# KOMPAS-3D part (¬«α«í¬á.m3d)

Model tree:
1. Эскиз:1
2. Операция выдавливания:1
     Расстояние 1 = 5
3. Скругление:1
     Радиус = 1
4. Эскиз:2
5. Операция выдавливания:2
     Расстояние 1 = 0.1
6. Скругление:2
     Радиус = 0.1
7. Эскиз:3
8. Операция выдавливания:3
     Расстояние 1 = 0.5
9. Эскиз:4
10. Операция выдавливания:4
     Расстояние 1 = 1
11. Эскиз:5
12. Операция выдавливания:5
     Расстояние 1 = 1
13. Эскиз:6
14. Операция выдавливания:6
     Расстояние 1 = 2
15. Эскиз:7
16. Операция выдавливания:7
     Расстояние 1 = 0.2
17. Скругление:3
     Радиус = 0.2
18. Эскиз:8
19. Операция выдавливания:8
     Расстояние 1 = 0.2
20. Скругление:4
     Радиус = 0.2

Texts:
  Сплав АЛ8  ГОСТ 1583-93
